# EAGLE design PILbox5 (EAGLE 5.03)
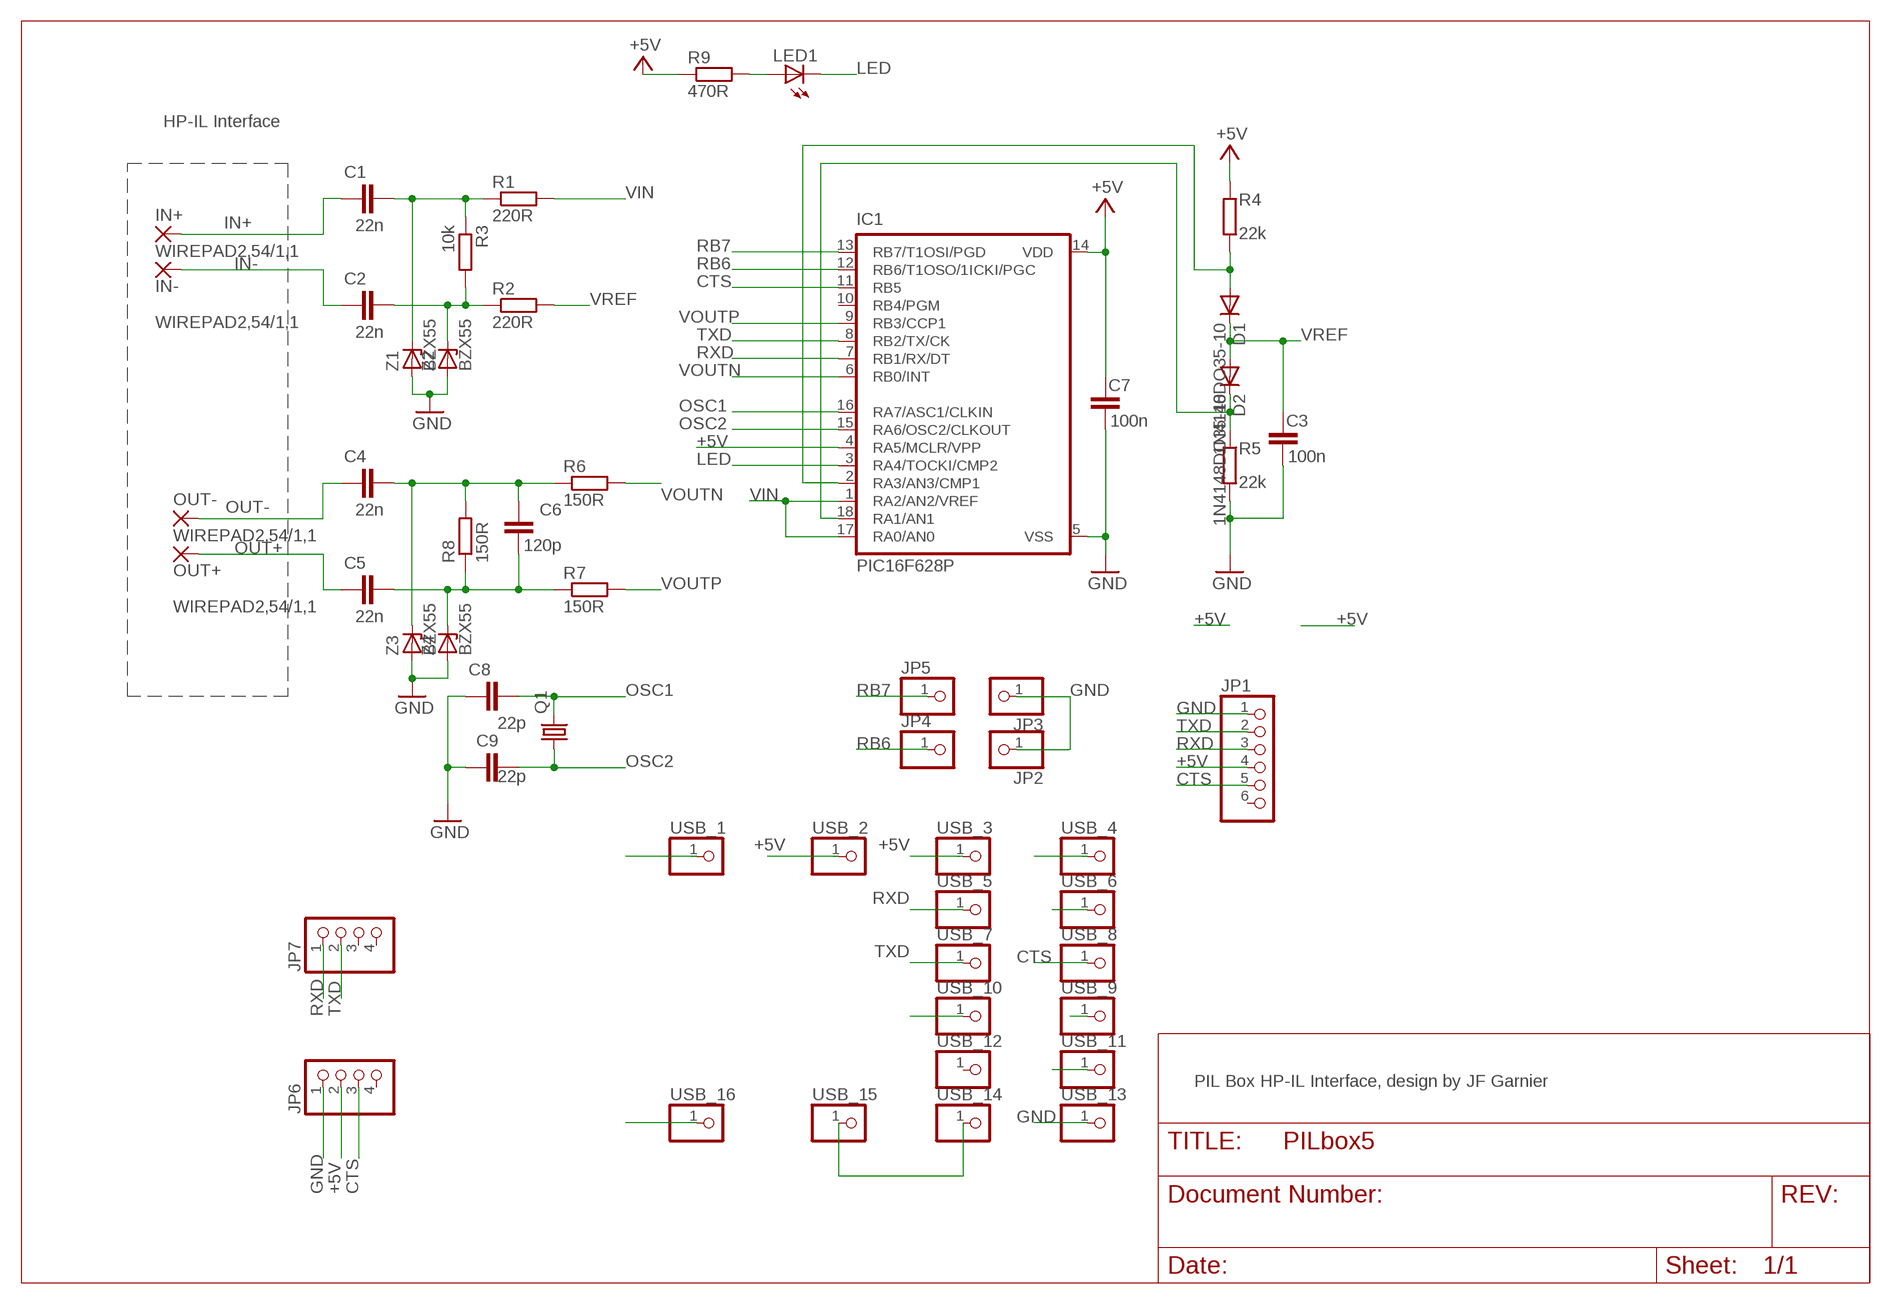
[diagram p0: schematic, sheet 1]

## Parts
C1  22n  C-EU050-025X075  [C050-025X075]
C2  22n  C-EU050-025X075  [C050-025X075]
C3  100n  C-EU050-025X075  [C050-025X075]
C4  22n  C-EU050-025X075  [C050-025X075]
C5  22n  C-EU050-025X075  [C050-025X075]
C6  120p  C-EU050-025X075  [C050-025X075]
C7  100n  C-EU050-025X075  [C050-025X075]
C8  22p  C-EU050-025X075  [C050-025X075]
C9  22p  C-EU050-025X075  [C050-025X075]
D1  1N4148DO35-10  [DO35-10]
D2  1N4148DO35-10  [DO35-10]
IC1  PIC16F628P  [DIL18]
IN+  WIREPAD2,54/1,1  [2,54/1,1]
IN-  WIREPAD2,54/1,1  [2,54/1,1]
JP1  PINHD-1X6  [1X06]
JP2  PINHD-1X1  [1X01]
JP3  PINHD-1X1  [1X01]
JP4  PINHD-1X1  [1X01]
JP5  PINHD-1X1  [1X01]
JP6  PINHD-1X4  [1X04]
JP7  PINHD-1X4  [1X04]
LED1  LED3MM  [LED3MM]
OUT+  WIREPAD2,54/1,1  [2,54/1,1]
OUT-  WIREPAD2,54/1,1  [2,54/1,1]
Q1  CRYSTALHC18U-V  [HC18U-V]
R1  220R  R-EU_0207/10  [0207/10]
R2  220R  R-EU_0207/10  [0207/10]
R3  10k  R-EU_0207/10  [0207/10]
R4  22k  R-EU_0207/10  [0207/10]
R5  22k  R-EU_0207/10  [0207/10]
R6  150R  R-EU_0207/10  [0207/10]
R7  150R  R-EU_0207/10  [0207/10]
R8  150R  R-EU_0207/10  [0207/10]
R9  470R  R-EU_0204/2V  [0204V]
USB_1  PINHD-1X1  [1X01]
USB_2  PINHD-1X1  [1X01]
USB_3  PINHD-1X1  [1X01]
USB_4  PINHD-1X1  [1X01]
USB_5  PINHD-1X1  [1X01]
USB_6  PINHD-1X1  [1X01]
USB_7  PINHD-1X1  [1X01]
USB_8  PINHD-1X1  [1X01]
USB_9  PINHD-1X1  [1X01]
USB_10  PINHD-1X1  [1X01]
USB_11  PINHD-1X1  [1X01]
USB_12  PINHD-1X1  [1X01]
USB_13  PINHD-1X1  [1X01]
USB_14  PINHD-1X1  [1X01]
USB_15  PINHD-1X1  [1X01]
USB_16  PINHD-1X1  [1X01]
Z1  BZX55  [DO35Z10]
Z2  BZX55  [DO35Z10]
Z3  BZX55  [DO35Z10]
Z4  BZX55  [DO35Z10]

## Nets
+5V [power]: C7.2 IC1.4(RA5/MCLR/VPP) IC1.14(VDD) JP1.4 JP6.2 R4.1 R9.1 USB_2.1 USB_3.1
CTS: IC1.11(RB5) JP1.5 JP6.3 USB_8.1
GND [power]: C3.1 C7.1 C8.1 C9.1 IC1.5(VSS) JP1.1 JP2.1 JP3.1 JP6.1 R5.2 USB_13.1 Z1.A Z2.A Z3.A Z4.A
IN+: C1.1 IN+.1(P)
IN-: C2.1 IN-.1(P)
LED: IC1.3(RA4/TOCKI/CMP2) LED1.K(C)
N$1: C1.2 R1.1 R3.1 Z1.C
N$2: C2.2 R2.1 R3.2 Z2.C
N$3: C4.2 C6.2 R6.1 R8.2 Z3.C
N$4: C5.2 C6.1 R7.1 R8.1 Z4.C
N$8: D1.A IC1.2(RA3/AN3/CMP1) R4.2
N$9: D2.C IC1.18(RA1/AN1) R5.1
N$10: LED1.A R9.2
N$12: USB_1.1
N$15: USB_4.1
N$17: USB_6.1
N$22: USB_9.1
N$23: USB_10.1
N$25: USB_11.1
N$29: USB_14.1 USB_15.1
N$32: USB_16.1
OSC1: C8.2 IC1.16(RA7/ASC1/CLKIN) Q1.2
OSC2: C9.2 IC1.15(RA6/OSC2/CLKOUT) Q1.1
OUT+: C5.1 OUT+.1(P)
OUT-: C4.1 OUT-.1(P)
RB6: IC1.12(RB6/T1OSO/1ICKI/PGC) JP4.1
RB7: IC1.13(RB7/T1OSI/PGD) JP5.1
RXD: IC1.7(RB1/RX/DT) JP1.3 JP7.1 USB_5.1
TXD: IC1.8(RB2/TX/CK) JP1.2 JP7.2 USB_7.1
VIN: IC1.1(RA2/AN2/VREF) IC1.17(RA0/AN0) R1.2
VOUTN: IC1.6(RB0/INT) R6.2
VOUTP: IC1.9(RB3/CCP1) R7.2
VREF: C3.2 D1.C D2.A R2.2
Unconnected: IC1.10(RB4/PGM) JP1.6 JP6.4 JP7.3 JP7.4 USB_12.1

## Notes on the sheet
- HP-IL Interface
- PIL Box HP-IL Interface, design by JF Garnier

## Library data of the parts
C1-C9 = rcl:C-EU: CAPACITOR, European symbol
D1 D2 = diode:1N4148: DIODE
IC1 = microchip:PIC16*F62: FLASH-Based 8-Bit CMOS Microcontroller Source: http://ww1.microchip.com/downloads/en/DeviceDoc/40300C.pdf
IN+ IN- OUT+ OUT- = wirepad:WIREPAD: Wire PAD connect wire on PCB
JP1 = pinhead:PINHD-1X6: PIN HEADER
JP2-JP5 USB_1-USB_16 = pinhead:PINHD-1X1: PIN HEADER
JP6 JP7 = pinhead:PINHD-1X4: PIN HEADER
LED1 = led:LED: LED
Q1 = crystal:CRYSTAL: CRYSTAL
R1-R9 = resistor:R-EU_: RESISTOR, European symbol
Z1-Z4 = diode:BZX55: Z DIODE

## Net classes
0 default: width 0.203 mm, clearance 0.203 mm
1 power: width 0.254 mm, clearance 0.254 mm

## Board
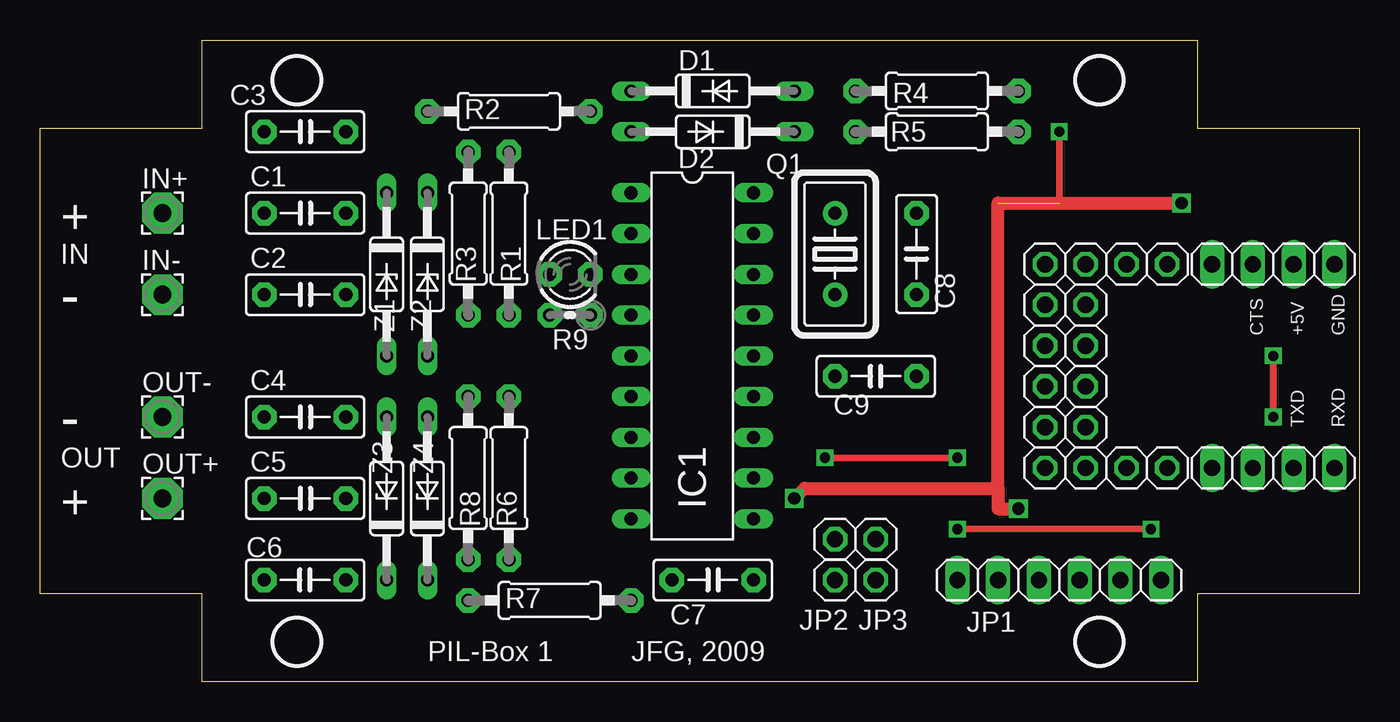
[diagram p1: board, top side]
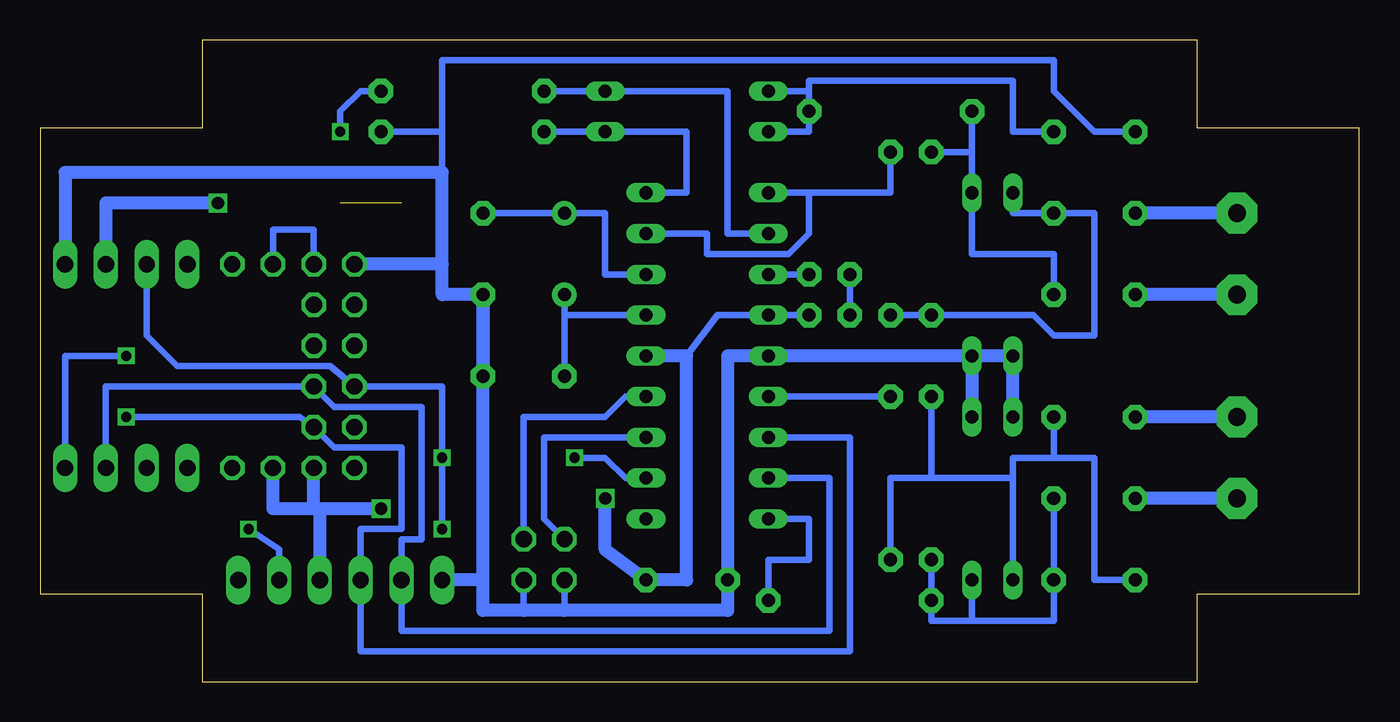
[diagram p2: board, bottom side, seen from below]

Size 82.2 x 40 mm. Coordinates in mm from the lower left corner, seen from the top.
Outline: 0,5.5 0,34.5 10.1,34.5 10.1,40 72.1,40 72.1,34.5 82.2,34.5 82.2,5.5 72.1,5.5 72.1,0 10.1,0 10.1,5.5 0,5.5
Copper layers (1*16): Top 0.035mm / dielectric 1.5mm / Bottom 0.035mm
Design rules "default *": minimum track width 8mil, minimum drill 24mil, track to track 8mil, track to pad 8mil, pad to pad 8mil, via to via 8mil, smd to smd 8mil, copper to edge 40mil, drill to drill 8mil, minimum pad ring 8mil, minimum via ring 8mil, stop-mask expansion 4mil, vias tented up to drill 0mil, thermal gap 10mil

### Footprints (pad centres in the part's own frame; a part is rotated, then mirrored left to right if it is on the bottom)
C050-025X075 = drill 0.813 pad 1.524 octagon: 1 -2.54,0; 2 2.54,0
DO35-10 = drill 0.813 long: A 5.08,0; C -5.08,0
DIL18 = drill 0.813 long: 1 -10.16,-3.81; 2 -7.62,-3.81; 3 -5.08,-3.81; 4 -2.54,-3.81; 5 0,-3.81; 6 2.54,-3.81; 7 5.08,-3.81; 8 7.62,-3.81; 9 10.16,-3.81; 10 10.16,3.81; 11 7.62,3.81; 12 5.08,3.81; 13 2.54,3.81; 14 0,3.81; 15 -2.54,3.81; 16 -5.08,3.81; 17 -7.62,3.81; 18 -10.16,3.81
2,54/1,1 = drill 1.118 pad 2.54 octagon: 1 0,0
1X06 = drill 1.016 long: 1 -6.35,0; 2 -3.81,0; 3 -1.27,0; 4 1.27,0; 5 3.81,0; 6 6.35,0
1X01 = drill 1.016 octagon: 1 0,0
1X04 = drill 1.016 long: 1 -3.81,0; 2 -1.27,0; 3 1.27,0; 4 3.81,0
LED3MM = drill 0.813 pad 1.524 octagon: A -1.27,0; K 1.27,0
HC18U-V = drill 0.813 pad 1.524 round: 1 -2.54,0; 2 2.54,0
0207/10 = drill 0.813 pad 1.524 octagon: 1 -5.08,0; 2 5.08,0
0204V = drill 0.813 pad 1.524 octagon: 1 -1.27,0; 2 1.27,0
DO35Z10 = drill 0.813 long: A 5.08,0; C -5.08,0

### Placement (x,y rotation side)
C1  16.51,29.21 0 top
C2  16.51,24.13 0 top
C3  16.51,34.29 0 top
C4  16.51,16.51 0 top
C5  16.51,11.43 0 top
C6  16.51,6.35 180 top
C7  41.91,6.35 0 top
C8  54.61,26.67 90 top
C9  52.07,19.05 180 top
D1  41.91,36.83 0 top
D2  41.91,34.29 180 top
IC1  40.64,20.32 270 top
IN+  7.62,29.21 0 top
IN-  7.62,24.13 0 top
JP1  63.5,6.35 0 top
JP2  49.53,6.35 0 top
JP3  52.07,6.35 0 top
JP4  49.53,8.89 0 top
JP5  52.07,8.89 0 top
JP6  76.83,26.04 180 top
JP7  76.83,13.34 180 top
LED1  33.02,25.4 0 top
OUT+  7.62,11.43 0 top
OUT-  7.62,16.51 0 top
Q1  49.53,26.67 90 top
R1  29.21,27.94 90 top
R2  29.21,35.56 0 top
R3  26.67,27.94 90 top
R4  55.88,36.83 180 top
R5  55.88,34.29 0 top
R6  29.21,12.7 90 top
R7  31.75,5.08 0 top
R8  26.67,12.7 90 top
R9  33.02,22.86 180 top
USB_1  70.23,13.34 0 top
USB_2  67.69,13.34 0 top
USB_3  65.15,13.34 0 top
USB_4  62.61,13.34 0 top
USB_5  65.15,15.88 0 top
USB_6  62.61,15.88 0 top
USB_7  65.15,18.41 0 top
USB_8  62.61,18.41 0 top
USB_9  62.61,20.95 0 top
USB_10  65.15,20.95 0 top
USB_11  62.61,23.5 0 top
USB_12  65.15,23.5 0 top
USB_13  62.61,26.04 0 top
USB_14  65.15,26.04 0 top
USB_15  67.69,26.04 0 top
USB_16  70.23,26.04 0 top
Z1  21.59,25.4 270 top
Z2  24.13,25.4 270 top
Z3  21.59,11.43 90 top
Z4  24.13,11.43 90 top

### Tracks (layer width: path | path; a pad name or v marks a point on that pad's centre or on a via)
+5V  (via drill 0.64, 0.76)  (1 unrouted)
  Top 0.406: 63.5,29.84 v63.5,34.29
  Top 0.813: v46.99,11.43 47.62,12.06 59.69,12.06 | v71.12,29.84 59.69,29.84 59.69,12.06 | 59.69,12.06 59.69,10.79 v60.96,10.79
  Bottom 0.406: 41.91,20.32 40.01,22.86 IC1.4 R9.1 | v63.5,34.29 63.5,35.56 62.23,36.83 R4.1
  Bottom 0.813: IC1.14 41.91,20.32 41.91,6.35 C7.2 46.99,8.26 v46.99,11.43 | USB_3.1 65.15,10.79 64.77,10.79 | USB_2.1 67.69,10.79 64.77,10.79 | v60.96,10.79 64.77,10.79 | JP6.2 78.11,29.84 v71.12,29.84 | 64.77,10.79 JP1.4
CTS  (via drill 0.64)
  Top 0.406: v57.15,9.53 v69.22,9.53 | v48.9,13.97 v57.15,13.97
  Bottom 0.406: IC1.11 45.72,12.7 46.99,13.97 v48.9,13.97 | v69.22,9.53 67.31,8.26 JP1.5 | v57.15,9.53 v57.15,13.97 57.15,18.41 USB_8.1 64.14,19.68 73.66,19.68 75.56,21.59 JP6.3
GND
  Bottom 0.406: 52.07,4.45 JP3.1 | 49.53,4.45 JP2.1 | 57.15,31.75 57.15,34.29 | C3.1 16.51,34.29 19.05,36.83 19.05,38.73 57.15,38.73 57.15,34.29 | 57.15,34.29 R5.2
  Bottom 0.813: Z2.A Z1.A Z3.A | Z2.A Z4.A | 54.61,6.35 54.61,4.45 52.07,4.45 49.53,4.45 39.37,4.45 C7.1 39.37,20.32 IC1.5 Z2.A | 54.61,6.35 C8.1 | C8.1 C9.1 C8.1 | C8.1 57.15,24.13 57.15,26.04 | 57.15,26.04 USB_13.1 | 57.15,26.04 57.15,31.75 80.64,31.75 JP6.1 | 54.61,6.35 JP1.1
IN+
  Bottom 0.813: IN+.1 C1.1
IN-
  Bottom 0.813: IN-.1 C2.1
LED
  Bottom 0.406: LED1.K IC1.3
N$1
  Bottom 0.406: R1.1 R3.1 20.32,22.86 19.05,21.59 16.51,21.59 16.51,29.21 C1.2 21.59,29.21 Z1.C
N$2
  Bottom 0.406: C2.2 19.05,26.67 24.13,26.67 Z2.C 24.13,33.02 | 24.13,33.02 R3.2 | 24.13,33.02 R2.1
N$3
  Bottom 0.406: 19.05,13.97 C4.2 | 21.59,12.7 Z3.C | 26.67,12.7 R8.2 | 21.59,12.7 26.67,12.7 | R6.1 29.21,12.7 26.67,12.7 | 19.05,13.97 16.51,13.97 16.51,6.35 C6.2 | 19.05,13.97 21.59,13.97 21.59,12.7
N$4
  Bottom 0.406: 26.67,6.35 R7.1 | 26.67,6.35 R8.1 | 24.13,3.81 Z4.C | 24.13,3.81 19.05,3.81 C6.1 C5.2 | 26.67,6.35 26.67,3.81 24.13,3.81
N$8
  Bottom 0.406: IC1.2 39.37,27.94 39.37,36.83 D1.A R4.2
N$9
  Bottom 0.406: R5.1 D2.C 41.91,34.29 41.91,30.48 IC1.18
N$10
  Bottom 0.406: R9.2 LED1.A
N$29
  Bottom 0.406: USB_14.1 65.15,28.19 67.69,28.19 USB_15.1
OSC1
  Bottom 0.406: IC1.16 46.99,25.4 46.99,29.21 Q1.2 C8.2
OSC2
  Bottom 0.406: C9.2 49.53,22.86 | 49.53,22.86 Q1.1 | 49.53,22.86 IC1.15
OUT+
  Bottom 0.813: OUT+.1 C5.1
OUT-
  Bottom 0.813: OUT-.1 C4.1
RB6
  Bottom 0.406: JP4.1 50.8,10.16 50.8,15.24 IC1.12
RB7
  Bottom 0.406: JP5.1 52.07,16.51 46.99,16.51 45.72,17.78 IC1.13
RXD  (via drill 0.64)
  Top 0.406: v76.83,20.32 v76.83,16.51
  Bottom 0.406: IC1.7 31.75,15.24 31.75,1.91 62.23,1.91 JP1.3 62.23,9.53 59.69,9.53 59.69,14.61 63.88,14.61 USB_5.1 66.04,16.51 v76.83,16.51 | JP7.1 80.64,20.32 v76.83,20.32
TXD
  Bottom 0.406: IC1.8 33.02,12.7 33.02,3.17 59.69,3.17 JP1.2 59.69,8.89 58.42,8.89 58.42,17.14 63.88,17.14 USB_7.1 78.11,18.41 JP7.2
VIN
  Bottom 0.406: IC1.17 40.64,27.94 40.64,26.67 35.56,26.67 34.29,27.94 34.29,30.48 | 34.29,30.48 29.21,30.48 R1.2 | 34.29,30.48 IC1.1
VOUTN
  Bottom 0.406: R6.2 IC1.6
VOUTP
  Bottom 0.406: IC1.9 34.29,10.16 34.29,7.62 36.83,7.62 R7.2
VREF
  Bottom 0.406: C3.2 21.59,34.29 21.59,37.47 34.29,37.47 34.29,36.83 | 34.29,36.83 R2.2 34.29,34.29 D2.A | 34.29,36.83 D1.C

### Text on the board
tPlace: + | IN | - | CTS | +5V | GND | TXD | RXD | - | OUT | + | PIL-Box 1 | JFG, 2009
